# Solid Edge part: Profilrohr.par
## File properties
Username: bmolnar
Dokumentum tartalom típus: 0
Author: bmolnar
Last saved by: bmolnar
Revision: 80
Sűrűség: 0,000 kg/m^3
Pontosság: 0,990
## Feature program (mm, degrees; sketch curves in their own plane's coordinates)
base feature "unnamed BaseFeature 1"
thread "unnamed Thread 1"
thread "Menet_2"  ThreadDepth = 7.5 mm
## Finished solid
Body 1: solid body, 165 faces, 370 edges, 228 vertices, 3 separate solids.
  Faces by surface: plane 100, cylinder 43, cone 18, torus 4
  Edges by curve: line 256, circle 106, curve on surface 7, intersection 1
Bounding box of the edges (mm; curved faces can reach further): 80.000 x 86.000 x 62.000, from (-40, -40, 0) to (40, 46, 62).
Cylindrical faces by radius (mm): R1.6 x2, R4 x2, R4.283 x4, R4.55 x7, R4.555 x1, R6.9 x2, R7 x14, R31.5 x1, R32.35 x2, R32.55 x2, R34.1 x2, R53 x4
Conical faces (half-angle, radius in mm at the cone's reference point): 30 deg R31.825 x2, 30 deg R32.6387 x2, 45 deg R4.25 x4, 45 deg R4.533 x2, 45 deg R6.65 x4, 45 deg R32.7 x2, 45 deg R32.8 x2
Toroidal faces (ring radius, tube radius in mm): R33.9 r0.2 x4
Planar faces by outward normal: +x 9, +y 11, +z 12, -x 9, -y 9, -z 10, oblique 40
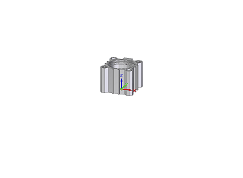
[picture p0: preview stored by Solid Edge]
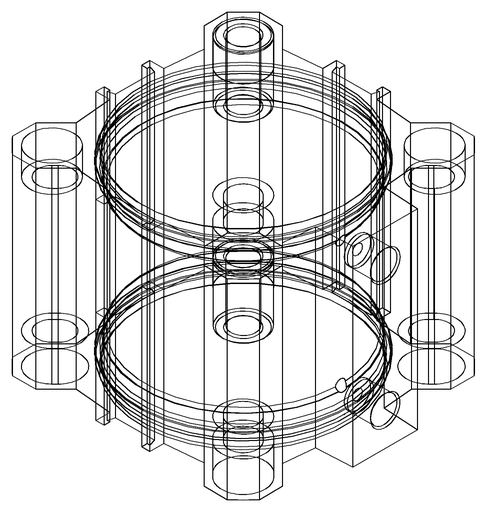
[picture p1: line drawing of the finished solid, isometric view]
